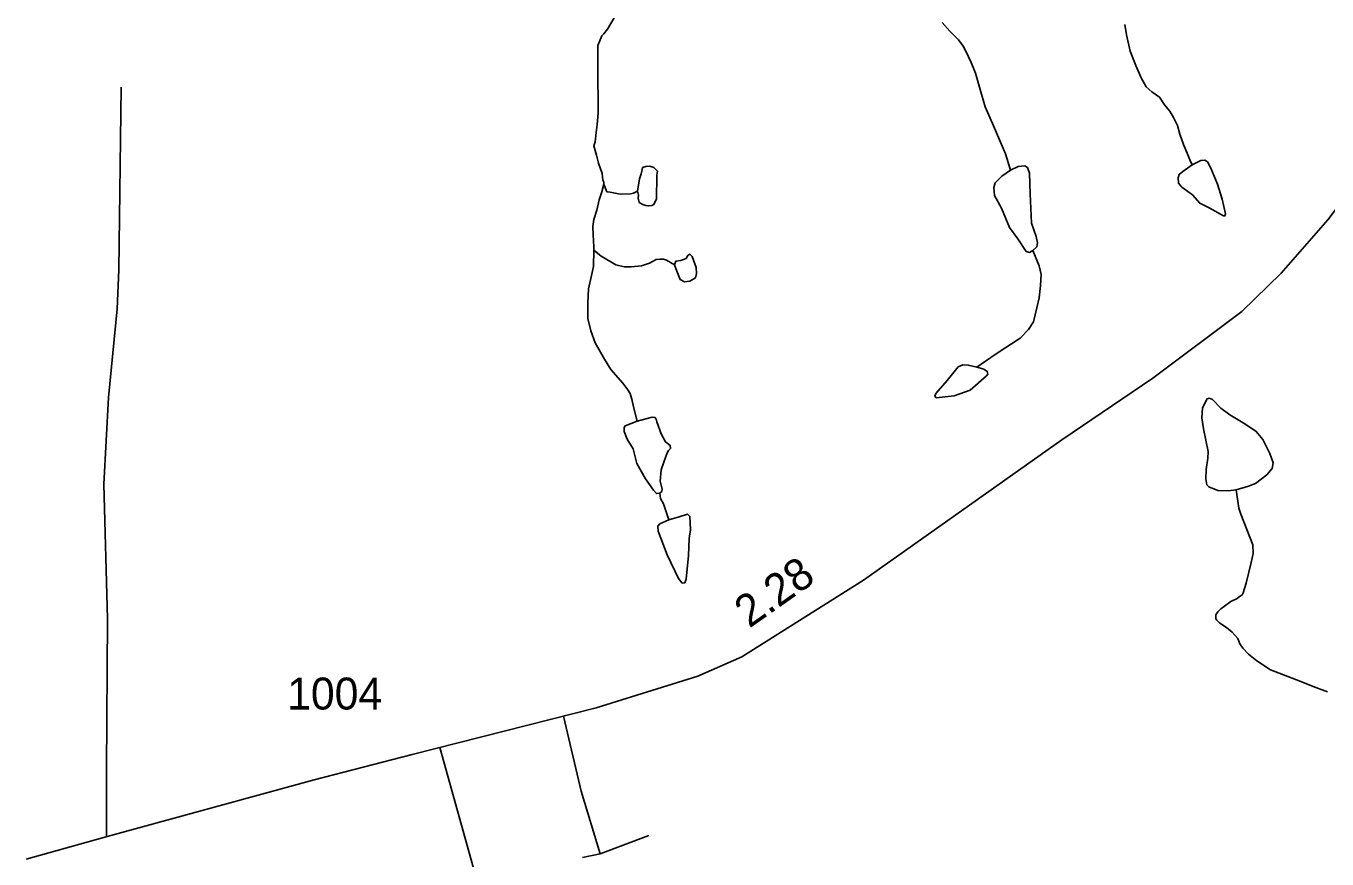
# Model space of a CAD drawing. Extents: x 2056842 to 2160602, y 826753 to 1016856.
# Drawn here: x 2083735 to 2088827, y 901949 to 905209 of the extents above; entities that cross this region are included whole.
import ezdxf

# ---------------------------------------------------------------- set-up
doc = ezdxf.new("R2010")
doc.units = 0
for name, color, linetype in [('Exist Hydrographic Misc Water Feature', 7, 'Continuous'), ('Exist Road Non-System Type 51', 7, 'Continuous'), ('Exist Road Secondary Mileage Hundredths English Label', 7, 'Continuous'), ('Exist Road Secondary Type 51 Attributed', 7, 'Continuous'), ('Exist Road Secondary Type 51 Number Label', 7, 'Continuous')]:
    doc.layers.add(name, color=color, linetype=linetype)

msp = doc.modelspace()

# ---------------------------------------------------------------- linework, layer by layer
at = {"layer": 'Exist Hydrographic Misc Water Feature'}
for points in [[(2085996.3, 904590.2), (2085996.3, 904598.2), (2085992.4, 904606.2), (2085990.1, 904632.2), (2085976, 904672.3), (2085968, 904704.1), (2085957.7, 904740.1), (2085961.8, 904756.1), (2085965.7, 904792.1), (2085969.6, 904824.2), (2085973.5, 904868.2), (2085972.9, 905052.1), (2085972.7, 905132.2), (2085988.5, 905170.2), (2085996.5, 905178.2), (2086010.4, 905196.3), (2086036.5, 905240.7), (2086065.2, 905294.4)], [(2087587.9, 904645.2), (2087567.8, 904709.1), (2087517.4, 904827), (2087489.3, 904892.9), (2087469, 904960.8), (2087450.7, 905024.7), (2087434.7, 905066.7), (2087412.6, 905110.7), (2087402.5, 905130.6), (2087384.5, 905154.5), (2087350.2, 905188.5), (2087320.1, 905222.3)], [(2088298.6, 904665.5), (2088289.8, 904685.4), (2088279.7, 904711.4), (2088265.6, 904745.4), (2088251.4, 904785.2), (2088241.4, 904819.2), (2088225.4, 904851.2), (2088211.3, 904875.2), (2088191.2, 904901.1), (2088171.1, 904931), (2088140.9, 904950.9), (2088119, 904970.8), (2088098.9, 905006.8), (2088078.6, 905054.7), (2088056.4, 905110.7), (2088042.3, 905174.5), (2088036.1, 905214.5)], [(2088298.6, 904665.5), (2088262.4, 904639.2), (2088248.7, 904628), (2088244.9, 904614.3), (2088246.2, 904594.3), (2088258.7, 904578.1), (2088299.8, 904548.1), (2088328.5, 904515.7), (2088365.9, 904497), (2088422.1, 904465.7), (2088427.1, 904465.7), (2088429.6, 904474.5), (2088417.1, 904531.9), (2088398.4, 904590.6), (2088372.2, 904653), (2088358.5, 904677.9), (2088348.5, 904684.2), (2088333.5, 904682.9), (2088298.6, 904665.5)], [(2086128.5, 904562.7), (2086132.4, 904546.7), (2086130.4, 904534.7), (2086134.5, 904518.7), (2086148.6, 904510.7), (2086160.5, 904506.8), (2086170.6, 904504.8), (2086184.5, 904506.9), (2086192.5, 904510.9), (2086202.4, 904532.9), (2086204.2, 904620.9), (2086204.2, 904624.9), (2086206.3, 904640.9), (2086192.1, 904654.8), (2086176.1, 904660.9), (2086160.1, 904658.8), (2086148, 904654.7), (2086146, 904646.7), (2086142.3, 904630.7), (2086136.1, 904610.7), (2086128.5, 904562.7)], [(2087587.9, 904645.2), (2087554.6, 904621.3), (2087528.4, 904595.1), (2087523.4, 904576.3), (2087525.9, 904545.1), (2087553.4, 904496.5), (2087584.6, 904420.3), (2087617, 904375.4), (2087649.4, 904326.7), (2087661.9, 904323), (2087675.6, 904330.5)], [(2087675.6, 904330.5), (2087690.6, 904344.2), (2087694.3, 904360.4), (2087688.1, 904385.4), (2087670.6, 904437.8), (2087665.6, 904552.6), (2087661.9, 904632.5), (2087654.4, 904655), (2087644.4, 904661.2), (2087618.2, 904658.7), (2087587.9, 904645.2)], [(2085957.1, 904332.2), (2085957.1, 904344.2), (2085954.9, 904392.2), (2085952.8, 904424.1), (2085956.7, 904452.1), (2085968.6, 904488.2), (2085978.4, 904528.2), (2085988.5, 904560.2), (2085996.3, 904590.2)], [(2086128.5, 904562.7), (2086120.5, 904558.7), (2086112.5, 904554.7), (2086100.4, 904552.6), (2086060.5, 904550.5), (2086020.5, 904558.4), (2086008.4, 904560.3), (2085996.3, 904590.2)], [(2086126.3, 903662), (2086113, 903718.7), (2086107, 903742.7), (2086098.8, 903770.6), (2086090.8, 903784.6), (2086070.7, 903810.5), (2086024, 903864.2), (2085999.1, 903905.3), (2085962.9, 903969), (2085946, 904016.1), (2085933.9, 904064.2), (2085933.7, 904124.1), (2085935.6, 904180), (2085947.5, 904232.1), (2085955.3, 904268.1), (2085957.1, 904332.2)], [(2086273.5, 904273.8), (2086241.1, 904293), (2086229.2, 904297), (2086217.1, 904296.9), (2086201.1, 904294.9), (2086187.2, 904286.9), (2086175.3, 904280.8), (2086143.3, 904270.8), (2086103.3, 904266.7), (2086075.2, 904266.6), (2086043.2, 904274.5), (2086023.1, 904286.4), (2085985.2, 904308.3), (2085957.1, 904332.2)], [(2087456.1, 903873.1), (2087528.2, 903923.1), (2087570.1, 903951.2), (2087592, 903965.3), (2087626, 903987.4), (2087658, 904021.5), (2087677.9, 904051.6), (2087691.6, 904105.5), (2087699.6, 904145.6), (2087705.4, 904193.6), (2087708.1, 904236.8), (2087700.6, 904270.5), (2087675.6, 904330.5)], [(2086273.5, 904273.8), (2086282.2, 904248.8), (2086294.7, 904216.4), (2086312.2, 904207.6), (2086333.4, 904210.1), (2086354.6, 904223.9), (2086359.6, 904240.1), (2086357.1, 904263.8), (2086342.1, 904306.2), (2086333.4, 904316.2), (2086324.7, 904311.2), (2086318.4, 904298.8), (2086297.2, 904291.3), (2086278.5, 904288.8), (2086273.5, 904273.8)], [(2087456.1, 903873.1), (2087483.5, 903865.7), (2087497.2, 903856.9), (2087499.7, 903846.9), (2087493.5, 903839.4), (2087429.9, 903783.3), (2087367.5, 903762.1), (2087297.7, 903753.3), (2087291.4, 903759.6), (2087296.4, 903770.8), (2087340.1, 903822), (2087383.7, 903874.4), (2087401.2, 903883.1), (2087422.4, 903881.9), (2087456.1, 903873.1)], [(2088471.1, 903393.7), (2088519.7, 903407.4), (2088547.2, 903418.7), (2088590.8, 903452.4), (2088612, 903477.3), (2088615.8, 903498.6), (2088603.3, 903536), (2088575.9, 903590.9), (2088549.7, 903622.1), (2088504.8, 903652.1), (2088446.1, 903687), (2088411.2, 903713.2), (2088378.8, 903746.9), (2088365, 903751.9), (2088357.6, 903749.4), (2088340.1, 903714.5), (2088336.3, 903675.8), (2088343.8, 903632.1), (2088352.6, 903588.4), (2088361.3, 903543.5), (2088360.1, 903517.3), (2088353.8, 903473.6), (2088352.6, 903436.2), (2088356.3, 903413.7), (2088363.8, 903404.9), (2088400, 903391.2), (2088439.9, 903390), (2088471.1, 903393.7)], [(2086126.3, 903662), (2086080.2, 903644.5), (2086076.4, 903637), (2086076.4, 903622), (2086087.7, 903592.1), (2086111.4, 903553.4), (2086125.1, 903497.2), (2086158.8, 903436), (2086191.2, 903392.4), (2086202.4, 903378.6), (2086216.1, 903381)], [(2086126.3, 903662), (2086185, 903678.2), (2086196.2, 903676.9), (2086201.2, 903670.7), (2086203.7, 903659.5), (2086221.1, 903613.3), (2086237.3, 903580.8), (2086256.1, 903567.1), (2086257.3, 903555.9), (2086249.8, 903547.1), (2086243.6, 903538.4), (2086231.1, 903502.2), (2086221.1, 903472.2), (2086217.4, 903427.3), (2086224.9, 903396.1), (2086223.6, 903387.4), (2086216.1, 903381)], [(2086216.1, 903381), (2086218.1, 903359.1), (2086230.2, 903339.1), (2086238.2, 903315.1), (2086251.1, 903275.7)], [(2088471.1, 903393.7), (2088481.9, 903322.1), (2088490.1, 903298.1), (2088536.5, 903178.3), (2088537.2, 903144.6), (2088529.7, 903109.6), (2088510.8, 903028.3), (2088499.1, 902990.2), (2088495, 902982.1), (2088483.2, 902974.1), (2088475.2, 902968.1), (2088451, 902956.1), (2088425.1, 902937.9), (2088411.2, 902927.9), (2088399.1, 902915.9), (2088391.3, 902903.9), (2088391.3, 902895.9), (2088391.3, 902887.9), (2088395.4, 902883.9), (2088407.5, 902871.9), (2088433.5, 902854), (2088455.5, 902836), (2088477.6, 902812.1), (2088485.6, 902790.2), (2088497.7, 902774.2), (2088519.7, 902750.3), (2088551.8, 902724.4), (2088606, 902688.6), (2088656, 902668.7), (2088724.1, 902643), (2088772.1, 902623.1), (2088828.3, 902603.2)], [(2086251.1, 903275.7), (2086216.1, 903260.7), (2086207.4, 903250.7), (2086208.7, 903232), (2086243.6, 903139.6), (2086288.5, 903046), (2086303.5, 903028.5), (2086313.4, 903029.8), (2086318.4, 903043.5), (2086327.2, 903137.1), (2086329.7, 903203.3), (2086335.9, 903238.2), (2086333.4, 903289.4), (2086323.4, 903298.1), (2086291, 903288.1), (2086251.1, 903275.7)]]:
    msp.add_lwpolyline(points, dxfattribs=at)
at = {"layer": 'Exist Road Non-System Type 51'}
for p, q in [((2085354.3, 902384.7), (2085512.7, 901815.8)), ((2085981.9, 901969.3), (2086172.6, 902040.8)), ((2085981.9, 901969.3), (2085913.4, 901954.4))]:
    msp.add_line(p, q, dxfattribs=at)
for points in [[(2084050, 902035.4), (2084050, 902298.7), (2084052.9, 902889), (2084039.5, 903415.2), (2084057.4, 903755), (2084091.7, 904102.3), (2084097.6, 904254.3), (2084106.6, 904969.8)], [(2085838.2, 902507.1), (2085907.4, 902213.7), (2085981.9, 901969.3)]]:
    msp.add_lwpolyline(points, dxfattribs=at)
at = {"layer": 'Exist Road Secondary Type 51 Attributed'}
msp.add_lwpolyline([(2083734.6, 901947.3), (2084066, 902039.9), (2084862.7, 902258.3), (2085245.4, 902357.2), (2085966.6, 902539.6), (2086363.6, 902663.7), (2086536.1, 902739.2), (2087012.1, 903039.4), (2087789, 903588.6), (2088144.7, 903831.2), (2088494.1, 904091), (2088646.8, 904242), (2088830.1, 904450.5), (2089001.6, 904676.1), (2089118.4, 904872.1), (2089236, 905095.9)], dxfattribs=at)

# ---------------------------------------------------------------- texts
at = {"layer": 'Exist Road Secondary Mileage Hundredths English Label'}
msp.add_text('2.28', height=125, rotation=35.2552, dxfattribs=at).set_placement((2086565.6, 902849.8))
at = {"layer": 'Exist Road Secondary Type 51 Number Label'}
msp.add_text('1004', height=125, dxfattribs=at).set_placement((2084756.8, 902533.5))

doc.saveas('drawing.dxf')
